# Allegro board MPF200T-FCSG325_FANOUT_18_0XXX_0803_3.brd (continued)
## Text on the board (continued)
Ref Des/Silkscreen Top: GND | VBUS | B10 | C12 | DIP3 | DIP4 | DIP1 | DIP2 | DIP5 | NC | RSTB | TDO | TCK | TMS | TDI | nTRST | VDDI4 | W3 | N2 | J9 | E1 | D4 | H2 | C4 | J6 | R1 | K9 | K6 | E9 | B8 | E8 | D9 | B7 | C6 | A8 | D7 | A6 | A7 | C7 | D8 | P2 | T1 | B1 | J3 | D3 | J1 | C9 | F2 | D1 | A2 | F1 | AB3 | J2 | C1 | MIPI-J7_A5 | MIPI-H7_B4 | B2 | V1 | H1 | E5 | G2 | V2 | B3 | U4 | L2 | K3 | A3 | W2 | U5 | F5 | E4 | W1 | B12 | F3 | AB4 | Y1 | A10 | T5 | A12 | AA1 | E13 | T6 | V4 | G5 | A11 | A15 | U2 | M8 | B13 | E3 | A13 | U3 | AA8 | A16 | M9 | D13 | AA15 | D16 | E15 | Y8 | F15 | R15 | W17 | T15 | D17 | Y15 | E16 | F16 | G20 | R19 | AB17 | W16 | V16 | G19 | G15 | F17 | C11 | AA17 | V17 | H15 | R20 | U17 | G17 | TRST | F8 | H13 | G14 | ALERT# | AGND | SDA | SCL | U19 | U20 | T17 | RESET | VDDI3 | G5M_RST_R | 12P0V | VDDSREF | EXT_VREF | 3P3V | VDDI1 | VDDI2 | VDDA | VDDAUX2 | VDDAUX4 | VDDI0 | VDD | VDD18 | VDD25 | VDDA25 | 12P0V_EXT | RVI HEADER | VREF_B4_L8 | VREF_B5_H5 | GND_B5 | B0_U5 | GND_B4 | B4_R1 | B2_C9 | SIG | GND_B0 | VDDA25_DUT | B1_W17 | RXP_0 | TXP_3 | TXP_1 | TXP_0 | RXP_1 | GND_B2 | SERDES0_RX_1 | SERDES0_RX_0 | SERDES0_TX_0 | CLK_P | SERDES0_TX_3 | SERDES0_TX_1 | S0_Int_Ref_CLK | TXN_3 | RXN_0 | TXN_1 | TXN_0 | RXN_1 | CLK_N | GND_B1 | TXN_2 | RXN_3 | RXN_2 | PCI_CORELIS | SERDES0_RX_3 | SERDES0_RX_2 | SERDES0_TX_2 | TXP_2 | RXP_3 | RXP_2 | FP4 HEADER | ON | VDDA_DUT | OFF | VREF_B2_C10 | VDD_EXT | B2_C11 | VDD25_DUT | AA16 | Y16 | T16 | R16 | S1_Int_Ref_CLK | S0_Ext_Ref_CLK | MPF200/100T-FCG484-IO-FMAX-BOARD_REV-1 | DVP-102-000510-001
L2_GND1: 02_GND1
L3_SIG1: 03_SIG1
L4_PWR: 04_PWR
L5_GND2: 05_GND2
DIMENSION: REV | A | INTIAL RELEASE | DESCRIPTION | REVISIONS | APR-2018 | DATE | APPROVAL | NOTE 20 | NOTE : FINISHED TRACE WIDTH,AIR GAP OF 100 OHM DIFFERENTIAL AND 50 OHM SIGNLE ENDED | LAYER | 15.  NO VENDOR LOGO, ART WORKS SHOULD NOT BE | 10.  THIS IS A ROHS COMPLIANT BOARD | 11.  BOARD MUST BE UL 94V-1 APPROVED. | 17.  DO NOT REMOVE UNUSED PADS IN INTERNAL LAYERS. | 19.  WARP & TWIST: SHALL NOT EXCEED 0.005 INCHES PER INCH | 20.  NEED RECTANGLE SLOT AS MENTIONED DIMENSION IN THE DRILL TABLE. | 14.  IMPEDANCE TOLERANCE.REFER IMPEDANCE TABLE | 16.  DEBURR ALL SHARP EDGES | 21.  ALL  8 MIL ,10 MIL & 15.75 MIL VIAS  NEED NON CONDUCTIVE VIA PLUGGING | 22.  IF REQUIRED CAN IGNORE THE TRACES THAT ARE <0.5 INCH FOR TDR MEASUREMENT. | 23.  NICKEL CONTENT ON OUTER LAYERS SHOULD BE VERY MINIMAL POSSIBLE | 24.  ALL THE TRACE WIDTH MENTIONED IN IMPEDANCE TABLE ARE FINISHED TRACE WIDTH | 25.  THEIVING IS OPTIONAL. IF ADDED IT NEED TO BE KEPT AWAY FROM ANY CONDUCTORS | 12.  FABRICATE BOARD PER IPC-A-600D STANDARD. | 13.  CLIP SILKSCREEN ON NO MASK AREA. | 18.  BOARD DIMENSIONS ARE IN INCH(MM). | L12_SIG4 | L14_SIG5 | L16_SIG6 | 26.  INTENTIONAL NET SHORTS: YES / NO, REFER INTENTIONAL_NET_SHORTS.TXT FILE | WITHOUT PRIOR APPROVAL FROM PACTRON. | DIELECTRIC GLASS STYLE SHOULD NOT BE CHANGED | 6.  SILKSCREEN BOTH SIDES, NON CONDUCTIVE WHITE INK. | 8.  SOLDER MASK TOP AND BOTTOM SIDES WITH | 7.  FABRICATE PER DIMENSIONS SHOWN. | 3.  GENERAL PLATING : APPLY GOLD < 5 MICROINCHES OVER NICKEL < 200 MICROINCHES | MINIMUM PLATING FOR ALL HOLES NEED TO BE 0.001" Cu | L3_SIG1 | L5_SIG2 | L7_SIG3 | 1.  MATERIAL:  REFER STACKUP TABLE | 2.  BOARD TO BE SOLDER MASK OVER BARE COPPER, | 5.  HOLE SIZES ARE AFTER PLATING. | 4.  ALL HOLES ARE PLATED THRU UNLESS OTHERWISE SPECIFIED | 9.  TOTAL BOARD THICKNESS: 97 mil +/-8 MIL | SOLDER MASK.  COLOR GREEN. | LIQUID PHOTO IMAGABLE OR DRY FILM | 18 LAYER CONSTRUCTION. | BOTTOM | NOTES: UNLESS OTHERWISE SPECIFIED | NOTE : | TOP | 3.1. SELECTIVE HARD GOLD PLATING (TOP ONLY) FOR SOCKET PADS TO BE FLAT & | SHOULD NOT BE CHANGED FROM ABOVE STATED VALUES. | FOR SELECTIVE PLATING SEE BELOW | AFTER PLUGGING THESE VIAS SHOULD BE FLAT AND SMOOTH ON BOTH TOP AND BOTTOM SIDES. | TRY TO ACHIEVE THICKNESS IN OUTER LAYER METAL WITH MORE COPPER INSTEAD OF MORE NICKEL | THERE SHOULD NOT BE ANY DEVIATIONS IN TRACE WIDTH AFTER MANUFACTURING | CHANGED WITHOUT PRIOR APPROVAL FROM PACTRON | BUT SETUP NEED TO BE DONE TO MEET IMPEDANCE REQUIREMENT | BY 300 MIL AFTER APPROVAL FROM PACTRON | GOLD PLATING ON PAD SHOULD BE THE SAME LEVEL OR | ABOVE THE SOLDER RESIST SURFACE ON TOP. | PLATED 50-100uIN(MINIMUM) OF Au OVER 150-200uIN OF Ni. | 4 MIL | 8 MIL | 50 OHM | REFER STACKUP | 3.5/6.5/3.5 MIL | 4.5/4.5/4.5 MIL | 7.5/13/7.5 MIL | 4.5/4/4.5 MIL | 100 OHM | 7.9/6.1/7.9 MIL | 90 OHM | (KNOOP HARDNESS 130~200) | TOLERANCE(%) | +/-10.0 | +/-5.0 | IMPEDANCE | IMPEDANCE TABLE: | B | D | C | 8 | 7 | 6 | 5 | 4 | 3 | 2 | 1
User.26: DATE: | FILM LAYER: | NAME: | AUG 2018 | MPF200T-FCSG325_FANOUT_STUDY | REV: | 1 | PACTRON
User.27: FAB | PROJECT NAME | PART NUMBER | ORIGINATOR | PACTRON | DATE | 3000 PATRICK HENRY DRIVE, SANTA CLARA, CA 95054. | 408-329-5500(PHONE), 408-747-1239(FAX). | 305-PD-18-0223 | APR 2018 | DVP-101-000510-001 | MPF200/100T-FCG484-IO-FMAX-BOARD | REV : | 1
User.30: TOTAL THICKNESS: 97 mils +/-8 mils | DIELECTRIC | TOP (0.5 oz + PLATING) | L2_GND1 (0.5 oz) | L3_SIG1 (0.5 oz) | L4_GND2 (0.5 oz) | L5_SIG2 (0.5 oz) | L6_GND3 (0.5 oz) | L7_SIG3 (0.5 oz) | L8_GND4 (0.5 oz) | L9_PWR1 (1.0 oz) | L10_PWR2 (1.0 oz) | L11_GND5 (0.5 oz) | L12_SIG4 (0.5 oz) | L13_GND6 (0.5 oz) | L14_SIG5 (0.5 oz) | L15_GND7 (0.5 oz) | L16_SIG6 (0.5 oz) | L17_GND8 (0.5 oz) | BOTTOM (0.5 oz + PLATING) | N4000-13SI | STACKUP: 18 LAYERS
User.36: FIGURE | SIZE | 6.0 | 8.0 | 28.0 | DRILL CHART: TOP to BOTTOM | ALL UNITS ARE IN MILS | TOLERANCE | +3.0/-3.0 | +2.0/-2.0 | PLATED | QTY | 137 | 4 | 97 | 10
